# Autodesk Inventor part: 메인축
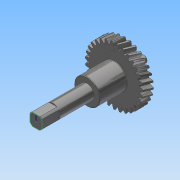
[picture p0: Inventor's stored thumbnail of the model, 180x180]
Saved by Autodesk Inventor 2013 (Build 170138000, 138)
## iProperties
Created: 2017-11
Part Number: 메인축
Material: 강철, 탄소
Document SubType Name: Modeling
Designer: mduedu
Categories: <?xml version="1.0" encoding="UTF-16"?> <MemberInstance><Categories><FamilyTemplate><FamilyTemplateParameter ValueType="xs:double" Id="1" ObjectReferenceKey="da
Density: 7.87 g/cm^3
Mass: 607.365 g
Surface Area: 183.17 cm^2
Volume: 77.1747 cm^3
CustomPartVersion: 1
Author: mduedu
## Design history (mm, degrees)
sketch "Sketch1"
  geometry: C1 r 34.094 at (0, 0)
  constraints: 1 centre point
  dimensions: "d0" = 68.18712 diameter of C1 (= da_da)
extrude "Extrusion1" new body sketch "Sketch1" distance "d1" = 12 (= da_b); taper "d2" = 0 deg
workplane "Work Plane2"
sketch "Sketch2"
  geometry: C1 r 34.094 at (0, 0) reference; C2 r 32.094 at (0, 0)
  constraints: 1 centre point, 1 coincident
  dimensions: "d3" = 64.18712 diameter of C2 (= da_dw)
feature "피치 지름" sketch "Sketch2" dims "d4" = 10, "d5" = 0
workplane "Work Plane8"
workplane "Work Plane9"
feature "스퍼 기어" dims "da_b" = 12, "da_d" = 64.18712, "da_aw" = 54.86964, "da_da" = 68.18712, "da_df" = 59.18712, "da_dw" = 64.18712, angle "da_beta" = 15 deg, "da_lefttooth" = 0, "da_righttooth" = 10
sketch "스케치3"
  geometry: C1 r 15 at (0, 0); 1 further point
  constraints: 1 centre point, 1 coincident
  dimensions: "d49" = 30 diameter of C1
extrude "돌출2" join sketch "스케치3" distance "d50" = 32; taper "d51" = 0 deg
sketch "스케치4"
  geometry: C1 r 8.5 at (0, 0); 1 further point
  constraints: 1 centre point, 1 coincident
  dimensions: "d52" = 17 diameter of C1
extrude "돌출3" join sketch "스케치4" distance "d53" = 60; taper "d54" = 0 deg
sketch "스케치5"
  geometry: C1 r 7.5 at (0, 0); 1 further point
  constraints: 1 centre point, 1 coincident
  dimensions: "d55" = 15 diameter of C1
extrude "돌출4" join sketch "스케치5" distance "d56" = 16; taper "d57" = 0 deg
sketch "스케치6"
  geometry: C1 r 4 at (0, 0); 1 further point
  constraints: 1 centre point, 1 coincident
  dimensions: "d58" = 8 diameter of C1
extrude "돌출5" join sketch "스케치6" distance "d59" = 7; taper "d60" = 0 deg
chamfer "모따기1" distance "d61" = 0.5; stored, may be unused: second distance "d62" = 2, angle "d63" = 45 deg
fillet "모깎기1" dims "d64" = 0.5
sketch "스케치7"
  geometry: L1 (-7, -7)-(7, -7); L2 (7, -7)-(7, 7); L3 (7, 7)-(-7, 7); L4 (-7, 7)-(-7, -7); L5 (-7, -7)-(7, 7); L6 (7, -7)-(-7, 7); L7 (-10, -10)-(10, -10); L8 (10, -10)-(10, 10); L9 (10, 10)-(-10, 10); L10 (-10, 10)-(-10, -10); L11 (-10, -10)-(10, 10); L12 (10, -10)-(-10, 10); 1 further point
  constraints: 24 end point, 4 midpoint, 4 parallel, 2 horizontal, 2 perpendicular
  dimensions: "d65" = 14 distance of L3.end L2.end; "d66" = 14 distance of L2.end L1.end; "d67" = 20 distance of L9.end L8.end; "d68" = 20 distance of L8.end L7.end
extrude "돌출6" cut sketch "스케치7" distance "d69" = 20; taper "d70" = 0 deg
sketch "스케치8"
  geometry: L1 (7, -3.873)-(7, 3.873) reference; L2 (3.873, 7)-(-3.873, 7) reference; L3 (-7, 3.873)-(-7, -3.873) reference; L4 (-3.873, -7)-(3.873, -7) reference; L5 (0, 0)-(0, 7); A1 r 8 centre (0, 0) between (7, 3.873) and (3.873, 7) reference; A2 r 8 centre (0, 0) between (-3.873, 7) and (-7, 3.873) reference; A3 r 8 centre (0, 0) between (-7, -3.873) and (-3.873, -7) reference; A4 r 8 centre (0, 0) between (3.873, -7) and (7, -3.873) reference
  constraints: 2 end point, 1 midpoint
body "Solid1"
body "Srf1"
other parameters: "d16" = 54.86964 (= da_aw), "d17" = 0, "d34" = 1.01342 (computed from da_z), "d39" = 0, "d41" = 0, "d43" = 54.86964 (= da_aw), "d46" = 54.86964 (= da_aw), "d47" = 0, "d48" = 0
